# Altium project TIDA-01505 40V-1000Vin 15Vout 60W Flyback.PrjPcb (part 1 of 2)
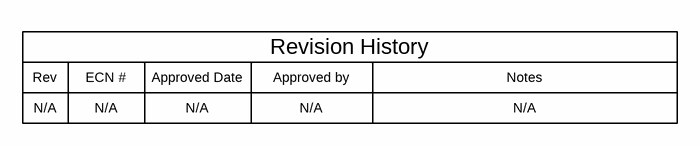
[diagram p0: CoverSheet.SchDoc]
CopyrightYear: 2017; PCB_Layout: X.Gong; PCB_Rev: E1; PRJ_Customer: Public Release; PRJ_Engineer: X.Gong; PRJ_Number: TIDA-01505; PRJ_Title: 40V-1000Vin 15Vout 60W Flyback; SCH_Rev: E1; TechSupport: http://www.ti.com/support; TID: TIDA-01505
4 sheets, 307 parts. Net scope: global (net labels, ports and power ports of the same name join across sheets).
Board file: TIDA-01505 PCB.PcbDoc
Sheets:
  CoverSheet.SchDoc
  Flyback_withOpto.SchDoc
  Flyback_PSR.SchDoc
  Hardware.SchDoc

## Sheet CoverSheet.SchDoc: Block Diagram
size A3; Date: Not shown in title block; ApprovedBy: Not shown in title block; CheckedBy: Not shown in title block; Author: Not shown in title block; CompanyName: Not shown in title block; DrawnBy: X.Gong; Engineer: Not shown in title block; Organization: Not shown in title block; Address1: Not shown in title block; Address2: Not shown in title block; Address3: Not shown in title block; Address4: Not shown in title block; DocumentNumber: 1; Revision: Use project parameter SCH_Rev; SheetNumber: 1; SheetTotal: 4; PageSetup: Record=PageOptions¦CenterHorizontal=True¦CenterVertical=True¦PrintScale=0.69¦XCorrection=1.00¦YCorrection=1.00¦PrintKind=0¦BorderSize=5000000¦LeftOffset=0¦BottomOffset=0¦Orientation=2¦PaperLength=1000¦PaperWidth=1000¦Scale=100¦PaperSource=15¦PrintQuality=600¦MediaType=1¦DitherType=10¦PaperKind=Letter¦PrintScaleMode=1

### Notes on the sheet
- Rev
- ECN #
- Approved Date
- Approved by
- Revision History
- Notes
- N/A

## Sheet Flyback_withOpto.SchDoc: Flyback_with_Optocoupler
size A3; Date: Not shown in title block; ApprovedBy: Not shown in title block; CheckedBy: Not shown in title block; Author: Not shown in title block; CompanyName: Not shown in title block; DrawnBy: X.Gong; Engineer: Not shown in title block; Organization: Not shown in title block; Address1: Not shown in title block; Address2: Not shown in title block; Address3: Not shown in title block; Address4: Not shown in title block; DocumentNumber: 1; Revision: Use project parameter SCH_Rev; SheetNumber: 3; SheetTotal: 4; PageSetup: Record=PageOptions¦CenterHorizontal=True¦CenterVertical=True¦PrintScale=0.69¦XCorrection=1.00¦YCorrection=1.00¦PrintKind=0¦BorderSize=5000000¦LeftOffset=0¦BottomOffset=0¦Orientation=2¦PaperLength=1000¦PaperWidth=1000¦Scale=100¦PaperSource=15¦PrintQuality=600¦MediaType=1¦DitherType=10¦PaperKind=Letter¦PrintScaleMode=1
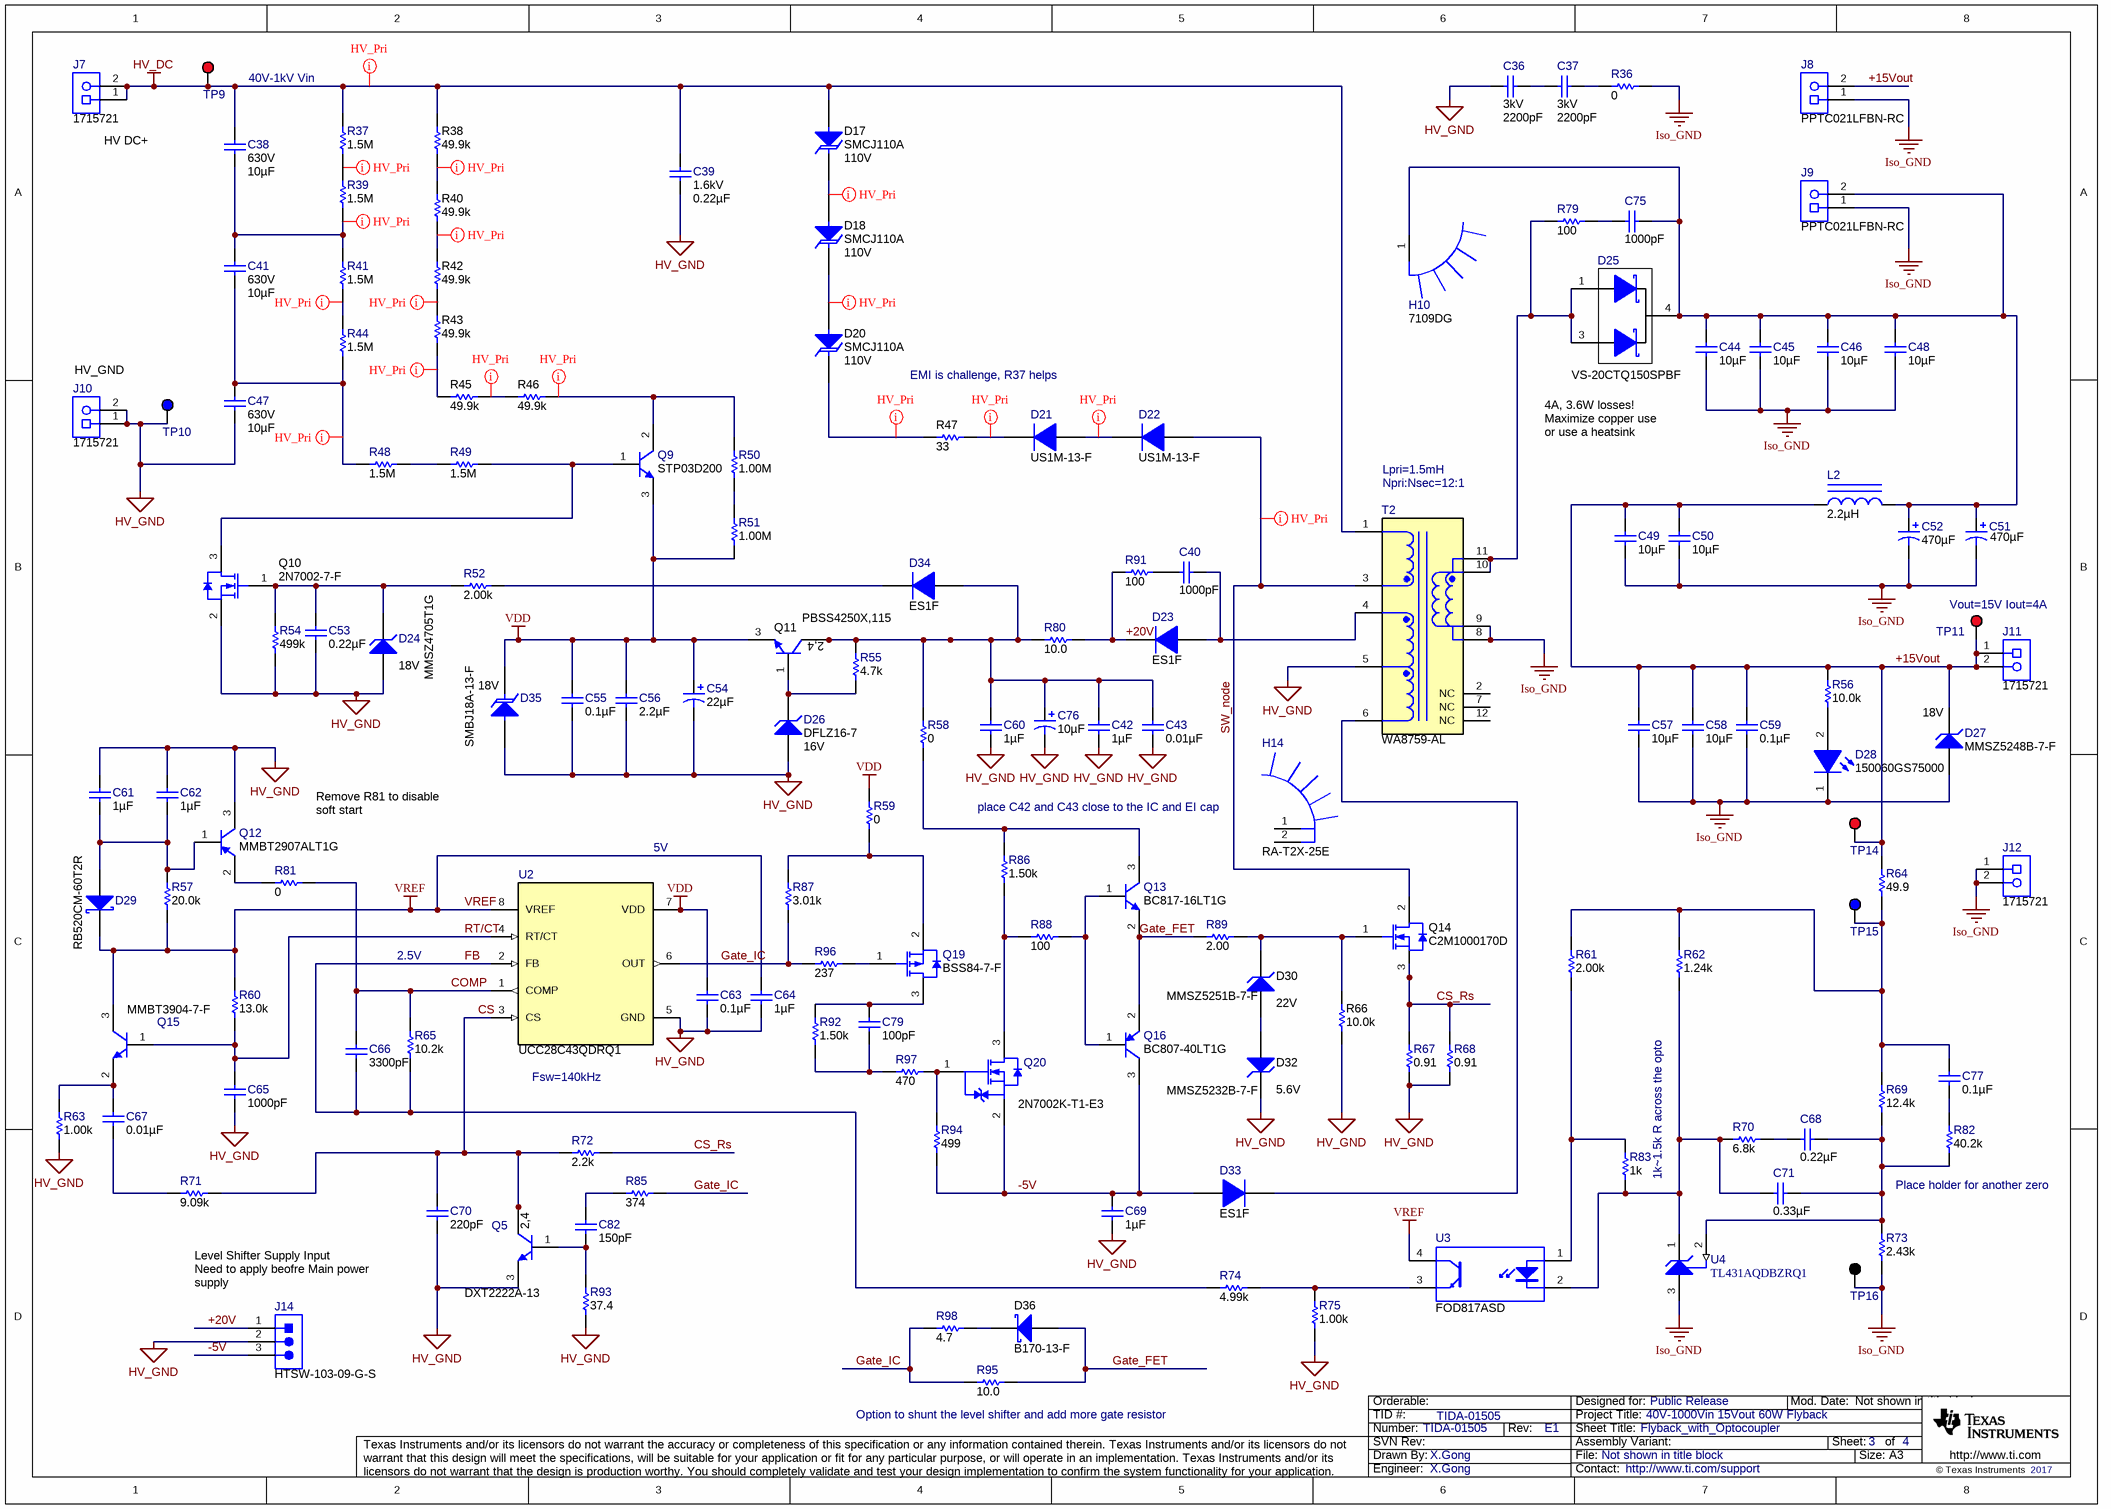
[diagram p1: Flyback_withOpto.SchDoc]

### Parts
C36  VDC_V: 3kV  ValueDisplayed: 2200pF  [CK45-RR_1650x600]  (hidden comment: CK45-R3FD222K-NRA)
C37  VDC_V: 3kV  ValueDisplayed: 2200pF  [CK45-RR_1650x600]  (hidden comment: CK45-R3FD222K-NRA)
C38  VDC_V: 630V  ValueDisplayed: 10µF  [B32776P_4200x1800x3250]  (hidden comment: B32776P6106K000)
C39  VDC_V: 1.6kV  ValueDisplayed: 0.22µF  [Kemet_3200x1800x3300]  (hidden comment: R76TR32204030J)
C40  ValueDisplayed: 1000pF  [1206]  (hidden comment: GRM31B5C2J102JW01L)
C41  VDC_V: 630V  ValueDisplayed: 10µF  [B32776P_4200x1800x3250]  (hidden comment: B32776P6106K000)
C42  ValueDisplayed: 1µF  [1206_180]  (hidden comment: GRM31CR72A105KA01L)
C43  ValueDisplayed: 0.01µF  [0805_HV]  (hidden comment: GRM21BR72A103KA01L)
C44  ValueDisplayed: 10µF  [0805_HV]  (hidden comment: GRM21BR6YA106KE43L)
C45  ValueDisplayed: 10µF  [0805_HV]  (hidden comment: GRM21BR6YA106KE43L)
C46  ValueDisplayed: 10µF  [0805_HV]  (hidden comment: GRM21BR6YA106KE43L)
C47  VDC_V: 630V  ValueDisplayed: 10µF  [B32776P_4200x1800x3250]  (hidden comment: B32776P6106K000)
C48  ValueDisplayed: 10µF  [0805_HV]  (hidden comment: GRM21BR6YA106KE43L)
C49  ValueDisplayed: 10µF  [0805_HV]  (hidden comment: GRM21BR6YA106KE43L)
C50  ValueDisplayed: 10µF  [0805_HV]  (hidden comment: GRM21BR6YA106KE43L)
C51  ValueDisplayed: 470µF  [Chemi-Con_1000x2000]  (hidden comment: EKZE350ELL471MJ20S)
C52  ValueDisplayed: 470µF  [Chemi-Con_1000x2000]  (hidden comment: EKZE350ELL471MJ20S)
C53  ValueDisplayed: 0.22µF  [0805_HV]  (hidden comment: GRM21BR71H224KA01L)
C54  ValueDisplayed: 22µF  [SM_RADIAL_D]  (hidden comment: EEE-FK1H220P)
C55  ValueDisplayed: 0.1µF  [0805_HV]  (hidden comment: C2012X7R1H104K085AA)
C56  ValueDisplayed: 2.2µF  [0805_HV]  (hidden comment: CGA4J3X7R1H225K125AB)
C57  ValueDisplayed: 10µF  [0805_HV]  (hidden comment: GRM21BR6YA106KE43L)
C58  ValueDisplayed: 10µF  [0805_HV]  (hidden comment: GRM21BR6YA106KE43L)
C59  ValueDisplayed: 0.1µF  [0805_HV]  (hidden comment: C2012X7R1H104K085AA)
C60  ValueDisplayed: 1µF  [1206_180]  (hidden comment: GRM31CR72A105KA01L)
C61  ValueDisplayed: 1µF  [0805_HV]  (hidden comment: GRM21BR71E105KA99L)
C62  ValueDisplayed: 1µF  [0805_HV]  (hidden comment: GRM21BR71E105KA99L)
C63  ValueDisplayed: 0.1µF  [0805_HV]  (hidden comment: C2012X7R1H104K085AA)
C64  ValueDisplayed: 1µF  [0603]  (hidden comment: GRM188R71E105KA12D)
C65  ValueDisplayed: 1000pF  [0805_HV]  (hidden comment: GCM2165C1H102JA16D)
C66  ValueDisplayed: 3300pF  [0805_HV]  (hidden comment: GRM2165C1H332JA01D)
C67  ValueDisplayed: 0.01µF  [0805_HV]  (hidden comment: GRM216R71H103KA01D)
C68  ValueDisplayed: 0.22µF  [0805_HV]  (hidden comment: GRM21BR71H224KA01L)
C69  ValueDisplayed: 1µF  [1206_180]  (hidden comment: GRM31CR72A105KA01L)
C70  ValueDisplayed: 220pF  [0805_HV]  (hidden comment: GRM2165C1H221JA01D)
C71  ValueDisplayed: 0.33µF  [0805_HV]  (hidden comment: GRM219R71H334KA88D)
C75  ValueDisplayed: 1000pF  [1206]  (hidden comment: GRM31B5C2J102JW01L)
C76  ValueDisplayed: 10µF  [SM_RADIAL_E]  (hidden comment: EEE-2AA100UP)
C77  ValueDisplayed: 0.1µF  [0805_HV]  (hidden comment: GCM21BR71H104KA37K)
C79  ValueDisplayed: 100pF  [0603]  (hidden comment: GRM1885C1H101JA01D)
C82  ValueDisplayed: 150pF  [0805_HV]  (hidden comment: GRM2165C1H151JA01D)
D17  SMCJ110A  value 110V  [SMC_265]
D18  SMCJ110A  value 110V  [SMC_265]
D20  SMCJ110A  value 110V  [SMC_265]
D21  US1M-13-F  [SMA]
D22  US1M-13-F  [SMA]
D23  ES1F  [SMA]
D24  MMSZ4705T1G  value 18V  [SOD-123]
D25  VS-20CTQ150SPBF  [DDPAK]
D26  DFLZ16-7  value 16V  [PowerDI123]
D27  MMSZ5248B-7-F  value 18V  [SOD-123]
D28  150060GS75000  [WL-SMCW_GREEN]
D29  RB520CM-60T2R  [SOD-923]
D30  MMSZ5251B-7-F  value 22V  [SOD-123]
D32  MMSZ5232B-7-F  value 5.6V  [SOD-123]
D33  ES1F  [SMA]
D34  ES1F  [SMA]
D35  SMBJ18A-13-F  value 18V  [SMB]
D36  B170-13-F  [SMA]
H10  7109DG  [Aavid_7109DG]
H14  RA-T2X-25E  [HSINK_RA-T2X-25E]
J7  1715721  [PhoenixContact_1715721]
J8  PPTC021LFBN-RC  [CONN_PPTC021LFBN-RC]
J9  PPTC021LFBN-RC  [CONN_PPTC021LFBN-RC]
J10  1715721  [PhoenixContact_1715721]
J11  1715721  [PhoenixContact_1715721]
J12  1715721  [PhoenixContact_1715721]
J14  HTSW-103-09-G-S  [Samtec_HTSW-103-09-x-S]
L2  ValueDisplayed: 2.2µH  [XAL6030]  (hidden comment: XAL6030-222MEB)
Q5  DXT2222A-13  [SOT-89-3]
Q9  STP03D200  [TO-220AB]
Q10  2N7002-7-F  [SOT-23]
Q11  PBSS4250X,115  [SOT-89-3]
Q12  MMBT2907ALT1G  [SOT-23]
Q13  BC817-16LT1G  [SOT-23]
Q14  C2M1000170D  [TO-247]
Q15  MMBT3904-7-F  [SOT-23]
Q16  BC807-40LT1G  [SOT-23]
Q19  BSS84-7-F  [SOT-23]
Q20  2N7002K-T1-E3  [SOT-23]
R36  ValueDisplayed: 0  [2010]  (hidden comment: CRCW20100000Z0EF)
R37  ValueDisplayed: 1.5M  [2010]  (hidden comment: ERJ12ZYJ155U)
R38  ValueDisplayed: 49.9k  [2010]  (hidden comment: CRCW201049K9FKEF)
R39  ValueDisplayed: 1.5M  [2010]  (hidden comment: ERJ12ZYJ155U)
R40  ValueDisplayed: 49.9k  [2010]  (hidden comment: CRCW201049K9FKEF)
R41  ValueDisplayed: 1.5M  [2010]  (hidden comment: ERJ12ZYJ155U)
R42  ValueDisplayed: 49.9k  [2010]  (hidden comment: CRCW201049K9FKEF)
R43  ValueDisplayed: 49.9k  [2010]  (hidden comment: CRCW201049K9FKEF)
R44  ValueDisplayed: 1.5M  [2010]  (hidden comment: ERJ12ZYJ155U)
R45  ValueDisplayed: 49.9k  [2010]  (hidden comment: CRCW201049K9FKEF)
R46  ValueDisplayed: 49.9k  [2010]  (hidden comment: CRCW201049K9FKEF)
R47  ValueDisplayed: 33  [2010]  (hidden comment: CRCW201033R0JNEF)
R48  ValueDisplayed: 1.5M  [2010]  (hidden comment: ERJ12ZYJ155U)
R49  ValueDisplayed: 1.5M  [2010]  (hidden comment: ERJ12ZYJ155U)
R50  ValueDisplayed: 1.00M  [2010]  (hidden comment: CRCW20101M00FKEF)
R51  ValueDisplayed: 1.00M  [2010]  (hidden comment: CRCW20101M00FKEF)
R52  ValueDisplayed: 2.00k  [0805_HV]  (hidden comment: CRCW08052K00FKEA)
R54  ValueDisplayed: 499k  [0603]  (hidden comment: CRCW0603499KFKEA)
R55  ValueDisplayed: 4.7k  [0603]  (hidden comment: CRCW06034K70JNEA)
R56  ValueDisplayed: 10.0k  [0603]  (hidden comment: CRCW060310K0FKEA)
R57  ValueDisplayed: 20.0k  [0805_HV]  (hidden comment: CRCW080520K0FKEA)
R58  ValueDisplayed: 0  [0805_HV]  (hidden comment: CRCW08050000Z0EA)
R59  ValueDisplayed: 0  [0805_HV]  (hidden comment: CRCW08050000Z0EA)
R60  ValueDisplayed: 13.0k  [0805_HV]  (hidden comment: CRCW080513K0FKEA)
R61  ValueDisplayed: 2.00k  [0805_HV]  (hidden comment: CRCW08052K00FKEA)
R62  ValueDisplayed: 1.24k  [0805_HV]  (hidden comment: CRCW08051K24FKEA)
R63  ValueDisplayed: 1.00k  [0805_HV]  (hidden comment: CRCW08051K00FKEA)
R64  ValueDisplayed: 49.9  [0805_HV]  (hidden comment: CRCW080549R9FKEA)
R65  ValueDisplayed: 10.2k  [0805_HV]  (hidden comment: CRCW080510K2FKEA)
R66  ValueDisplayed: 10.0k  [1206]  (hidden comment: CRCW120610K0FKEA)
R67  ValueDisplayed: 0.91  [2010]  (hidden comment: CRM2010-FX-R910ELF)
R68  ValueDisplayed: 0.91  [2010]  (hidden comment: CRM2010-FX-R910ELF)
R69  ValueDisplayed: 12.4k  [0805_HV]  (hidden comment: CRCW080512K4FKEA)
R70  ValueDisplayed: 6.8k  [0805_HV]  (hidden comment: CRCW08056K80JNEA)
R71  ValueDisplayed: 9.09k  [0805_HV]  (hidden comment: CRCW08059K09FKEA)
R72  ValueDisplayed: 2.2k  [0805_HV]  (hidden comment: CRCW08052K20JNEA)
R73  ValueDisplayed: 2.43k  [0805_HV]  (hidden comment: CRCW08052K43FKEA)
R74  ValueDisplayed: 4.99k  [0805_HV]  (hidden comment: CRCW08054K99FKEA)
R75  ValueDisplayed: 1.00k  [0805_HV]  (hidden comment: CRCW08051K00FKEA)
R79  ValueDisplayed: 100  [1206]  (hidden comment: CRCW1206100RFKEA)
R80  ValueDisplayed: 10.0  [1206]  (hidden comment: CRCW120610R0FKEA)
R81  ValueDisplayed: 0  [0805_HV]  (hidden comment: CRCW08050000Z0EA)
R82  ValueDisplayed: 40.2k  [0805_HV]  (hidden comment: CRCW080540K2FKEA)
R83  ValueDisplayed: 1k  [0805_HV]  (hidden comment: CRCW08052K05FKEA)
R85  ValueDisplayed: 374  [0805_HV]  (hidden comment: CRCW0805374RFKEA)
R86  ValueDisplayed: 1.50k  [2010]  (hidden comment: CRCW20101K50FKEF)
R87  ValueDisplayed: 3.01k  [0805_HV]  (hidden comment: CRCW08053K01FKEA)
R88  ValueDisplayed: 100  [0805_HV]  (hidden comment: CRCW0805100RFKEA)
R89  ValueDisplayed: 2.00  [2010]  (hidden comment: CRCW20102R00FKEF)
R91  ValueDisplayed: 100  [1206]  (hidden comment: CRCW1206100RFKEA)
R92  ValueDisplayed: 1.50k  [2010]  (hidden comment: CRCW20101K50FKEF)
R93  ValueDisplayed: 37.4  [0805_HV]  (hidden comment: CRCW080537R4FKEA)
R94  ValueDisplayed: 499  [0805_HV]  (hidden comment: CRCW0805499RFKEA)
R95  ValueDisplayed: 10.0  [1206]  (hidden comment: CRCW120610R0FKEA)
R96  ValueDisplayed: 237  [0805_HV]  (hidden comment: CRCW0805237RFKEA)
R97  ValueDisplayed: 470  [0805_HV]  (hidden comment: CRCW0805470RFKEA)
R98  ValueDisplayed: 4.7  [1206]  (hidden comment: CRCW12064R70JNEA)
T2  WA8759-AL  [Coilcraft_WA8537-BL]
TP9  5005  [Keystone5005]  (value not drawn)
TP10  5122  [Keystone5122]  (value not drawn)
TP11  5005  [Keystone5005]  (value not drawn)
TP14  5005  [Keystone5005]  (value not drawn)
TP15  5122  [Keystone5122]  (value not drawn)
TP16  5006  [Keystone5006]  (value not drawn)
U2  UCC28C43QDRQ1  [D0008A_N]
U3  FOD817ASD  [N04C]
U4  TL431AQDBZRQ1  [DBZ0003A_N]

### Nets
HV_DC: C38.1 C39.1 D17.2(A) J7.1 J7.2 R37.2 R38.2 T2.1 TP9.1
HV_GND: C36.2 C39.2 C42.2 C43.2 C47.2 C53.2 C54.2(-) C55.2 C56.2 C60.2 C61.1 C62.1 C63.2 C64.2 C65.2 C69.2 C70.2 C76.2(-) D24.2(A) D26.2(A) D32.1(K) D35.2(A) J10.1 J10.2 J14.2 Q5.3(E) Q10.2(S) Q12.3(C) R54.1 R63.1 R66.1 R67.1 R68.1 R75.1 R93.1 T2.5 TP10.1 U2.5(GND)
Iso_GND: C44.2 C45.2 C46.2 C48.2 C49.2 C50.2 C51.2(-) C52.2(-) C57.2 C58.2 C59.2 D27.2(A) D28.1(K) J8.1 J9.1 J12.1 J12.2 R36.2 R73.1 T2.8 T2.9 TP16.1 U4.3(ANODE)
VDD: C54.1(+) C55.1 C56.1 C63.1 D35.1(K) Q9.3(E) Q11.3(E) R51.1 R59.2 U2.7(VDD)
VREF: C64.1 D29.1(K) Q15.3(C) R57.1 R60.2 U2.8(VREF) U3.4(C)
+15Vout: C49.1 C50.1 C57.1 C58.1 C59.1 D27.1(K) J8.2 J11.1 J11.2 L2.1 R56.2 R64.2 TP11.1 TP14.1
+20V: D23.1(K) J14.1 R80.2 R91.1
-5V: C69.1 D33.2(A) J14.3 Q16.3(C) Q20.2(S) R94.1
COMP: C66.1 R65.2 R81.2 U2.1(COMP)
CS: C70.1 Q5.2(C) Q5.4(C) R71.2 R72.1 U2.3(CS)
CS_Rs: Q14.3(S) R67.2 R68.2 R72.2
FB: C66.2 R65.1 R74.1 U2.2(FB)
Gate_FET: D36.2(A) Q13.2(E) Q16.2(E) R89.1 R95.2
Gate_IC: R85.1 R87.1 R95.1 R96.1 R98.1 U2.6(OUT)
RT/CT: C65.1 Q15.1(B) R60.1 U2.4(RT/CT)
SW_node: D22.2(A) Q14.2(D) T2.3
NetC36_1: C36.1 C37.2
NetC37_1: C37.1 R36.1
NetC38_2: C38.2 C41.1 R39.1 R41.2
NetC40_1: C40.1 D23.2(A) T2.4
NetC40_2: C40.2 R91.2
NetC41_2: C41.2 C47.1 R44.1 R48.2
NetC42_1: C42.1 C43.1 C60.1 C76.1(+) D34.2(A) Q11.2(C) Q11.4(C) R55.2 R58.2 R80.1
NetC44_1: C44.1 C45.1 C46.1 C48.1 C51.1(+) C52.1(+) C75.1 D25.4(K) H10.1 J9.2 L2.2
NetC53_1: C53.1 D24.1(K) Q10.1(G) R52.1 R54.2
NetC61_2: C61.2 C62.2 D29.2(A) Q12.1(B) R57.2
NetC67_1: C67.1 Q15.2(E) R63.2
NetC67_2: C67.2 R71.1
NetC68_1: C68.1 C71.1 R69.1 R73.2 R82.1 U4.2(REF)
NetC68_2: C68.2 R70.2
NetC71_2: C71.2 R62.1 R70.1 R83.1 U3.2(K) U4.1(CATHODE)
NetC75_2: C75.2 R79.2
NetC77_1: C77.1 R61.2 R62.2 R64.1 R69.2 TP15.1
NetC77_2: C77.2 R82.2
NetC79_1: C79.1 Q19.3(D) R92.2
NetC79_2: C79.2 R92.1 R97.1
NetC82_1: C82.1 R85.2
NetC82_2: C82.2 Q5.1(B) R93.2
NetD17_1: D17.1(K) D18.2(A)
NetD18_1: D18.1(K) D20.2(A)
NetD20_1: D20.1(K) R47.1
NetD21_1: D21.1(K) R47.2
NetD21_2: D21.2(A) D22.1(K)
NetD25_1: D25.1(A) D25.3(A) R79.1 T2.10 T2.11
NetD26_1: D26.1(K) Q11.1(B) R55.1
NetD28_2: D28.2(A) R56.1
NetD30_1: D30.1(K) Q14.1(G) R66.2 R89.2
NetD30_2: D30.2(A) D32.2(A)
NetD33_1: D33.1(K) T2.6
NetD34_1: D34.1(K) R52.2
NetD36_1: D36.1(K) R98.2
NetQ9_1: Q9.1(B) Q10.3(D) R49.1
NetQ9_2: Q9.2(C) R46.1 R50.2
NetQ12_2: Q12.2(E) R81.1
NetQ13_1: Q13.1(B) Q16.1(B) R88.2
NetQ13_3: Q13.3(C) R58.1 R86.2
NetQ19_1: Q19.1(G) R96.2
NetQ19_2: Q19.2(S) R59.1 R87.2
NetQ20_1: Q20.1(G) R94.2 R97.2
NetQ20_3: Q20.3(D) R86.1 R88.1
NetR37_1: R37.1 R39.2
NetR38_1: R38.1 R40.2
NetR40_1: R40.1 R42.2
NetR41_1: R41.1 R44.2
NetR42_1: R42.1 R43.2
NetR43_1: R43.1 R45.2
NetR45_1: R45.1 R46.2
NetR48_1: R48.1 R49.2
NetR50_1: R50.1 R51.2
NetR61_1: R61.1 R83.2 U3.1(A)
NetR74_2: R74.2 R75.2 U3.3(E)

Not connected (* = marked no-connect by the designer): H14 1 2; T2 2(NC) 7(NC) 12(NC)

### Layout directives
net class 1500V: HV_DC, NetC38_2, NetC41_2, NetD17_1, NetD18_1, NetD20_1, NetD21_1, NetD21_2, NetQ9_2, NetR37_1, NetR38_1, NetR40_1, NetR41_1, NetR42_1, NetR43_1, NetR45_1, SW_node

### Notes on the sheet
- 40V-1kV Vin
- (near J7) HV DC+
- (near J10) HV_GND
- EMI is challenge, R37 helps
- 4A, 3.6W losses! Maximize copper use
  or use a heatsink
- (near T2) Npri:Nsec=12:1
- Lpri=1.5mH
- (near TP11) Vout=15V Iout=4A
- Remove R81 to disable soft start
- 5V
- place C42 and C43 close to the IC and EI cap
- 2.5V
- Fsw=140kHz
- (near R83) 1k
  .5k R across the opto
- Place holder for another zero
- Level Shifter Supply Input
  Need to apply beofre Main power supply
- (near R95) Option to shunt the level shifter and add more gate resistor

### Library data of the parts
C36 C37 = CMP-0074791-1: CAP, CERM, 2200 pF, 3000 V,+/- 10%, ?, 16.5x6mm; Manufacturer: TDK; TaMin_C: -25°C; Polarized: N; TempCo: R; SizeAreaWB_mm2: 148.0; U/M: EA; Value: 2200pF; TaMax_C: 125°C; SizeZ_mm: 20.5; SizeX_mm: 16.5; SizeY_mm: 6.0; Value2: 3000V; SizeArea_mm2: 99.0; Cap_F: 2.2nF; AEC Category: Q200
C38 C41 C47 = CMP-0074803-1: CAP, Film, 10 µF, 630 V,+/- 10%, 0.007 ohm, AEC-Q200 Grade 1, TH; Manufacturer: TDK; TaMin_C: -40°C; ESR_ohm: 7m; Polarized: N; SizeAreaWB_mm2: 880.0; U/M: EA; Value: 10uF; TaMax_C: 125°C; SizeZ_mm: 32.5; SizeX_mm: 42.0; SizeY_mm: 18.0; Cap_Case: 42x18x32.5mm; SizeArea_mm2: 756.0; AEC Qualified: Y; IRMS_A: 9.6A; AEC Grade: 1; AEC Category: Q200
C39 = CMP-0077096-1: CAP, Film, 0.22 µF, 1600 V,+/- 5%, AEC-Q200 Grade 2, TH; Manufacturer: Kemet; Cap_F: 220nF; SizeAreaWB_mm2: 680.0; SizeArea_mm2: 576.0; AEC Qualified: Y; AEC Category: Q200; Value: 0.22uF; TaMax_C: 105°C; SizeZ_mm: 33.1; AEC Grade: 2; Polarized: N; TaMin_C: -55°C; SizeY_mm: 18.0; Value2: 1600V; U/M: EA; SizeX_mm: 32.0; Cap_Case: 32x18x33mm
C40 C75 = GRM31B5C2J102JW01L: CAP, CERM, 1000 pF, 630 V,+/- 5%, C0G/NP0, 1206; Manufacturer: MuRata; Polarized: N; CompType: Capacitor; Value: 1000pF; U/M: EA; Cap_F: 0.000000001; Tolerance_%: 5; VDC_V: 630; Value2: 630V; TaMin_C: -55; TaMax_C: 125; SizeArea_mm2: 5.12; SizeAreaWB_mm2: 10.92; SizeX_mm: 3.2; SizeY_mm: 1.6; SizeZ_mm: 1.35; AEC Category: Q200; Green_Lifecycle: Not Set; Green_REACh: Incomplete
C42 C60 C69 = GRM31CR72A105KA01L: CAP, CERM, 1 µF, 100 V,+/- 10%, X7R, 1206; Manufacturer: MuRata; Polarized: N; CompType: Capacitor; Value: 1uF; U/M: EA; Cap_F: 0.000001; Tolerance_%: 10; VDC_V: 100; Value2: 100V; TaMin_C: -55; TaMax_C: 125; Cap_Case: 1206; SizeArea_mm2: 5.12; SizeAreaWB_mm2: 10.92; SizeX_mm: 3.2; SizeY_mm: 1.6; SizeZ_mm: 1.8; AEC Category: Q200; Green_Lifecycle: Active; Green_REACh: Passed
C43 = GRM21BR72A103KA01L: CAP, CERM, 0.01 µF, 100 V,+/- 10%, X7R, 0805; Manufacturer: MuRata; Polarized: N; CompType: Capacitor; Value: 0.01uF; U/M: EA; Cap_F: 0.00000001; Tolerance_%: 10; VDC_V: 100; Value2: 100V; TaMin_C: -55; TaMax_C: 125; Cap_Case: 0805; SizeArea_mm2: 2.5; SizeAreaWB_mm2: 6.75; SizeX_mm: 2; SizeY_mm: 1.25; SizeZ_mm: 1.45; AEC Category: Q200; Green_Lifecycle: Active; Green_REACh: Passed
C44-C46 C48-C50 C57 C58 = GRM21BR6YA106KE43L: CAP, CERM, 10 µF, 35 V,+/- 10%, X5R, 0805; Manufacturer: MuRata; Polarized: N; CompType: Capacitor; Value: 10uF; U/M: EA; Cap_F: 0.00001; Tolerance_%: 10; VDC_V: 35; Value2: 35V; TaMin_C: -55; TaMax_C: 85; Cap_Case: 0805; SizeArea_mm2: 2.5; SizeAreaWB_mm2: 6.75; SizeX_mm: 2; SizeY_mm: 1.25; SizeZ_mm: 1.45; AEC Category: Q200; Green_Lifecycle: Active; Green_REACh: Passed
C51 C52 = EKZE350ELL471MJ20S: CAP, AL, 470 µF, 35 V, +/- 20%, TH; Manufacturer: Chemi-Con; Polarized: Y; CompType: Capacitor; Value: 470uF; U/M: EA; Cap_F: 0.00047; Tolerance_%: 20; VDC_V: 35; Value2: 35V; IRMS_A: 1.82; TaMin_C: -40; TaMax_C: 105; Cap_Case: 10x20; SizeAreaWB_mm2: 144; SizeArea_mm2: 100; SizeX_mm: 10; SizeZ_mm: 21.5; AEC Category: Q200; AEC Qualified: N
C53 C68 = GRM21BR71H224KA01L: CAP, CERM, 0.22 µF, 50 V,+/- 10%, X7R, 0805; Manufacturer: MuRata; Polarized: N; CompType: Capacitor; Value: 0.22uF; U/M: EA; Cap_F: 0.00000022; Tolerance_%: 10; VDC_V: 50; Value2: 50V; TaMin_C: -55; TaMax_C: 125; Cap_Case: 0805; SizeArea_mm2: 2.5; SizeAreaWB_mm2: 6.75; SizeX_mm: 2; SizeY_mm: 1.25; SizeZ_mm: 1.45; AEC Category: Q200; Green_Lifecycle: Active; Green_REACh: Passed
C54 = EEE-FK1H220P: CAP, AL, 22 µF, 50 V, +/- 20%, 0.88 ohm, AEC-Q200 Grade 2, SMD; Manufacturer: Panasonic; Polarized: Y; CompType: Capacitor; Value: 22uF; U/M: EA; Cap_F: 0.000022; Tolerance_%: 20; VDC_V: 50; Value2: 50V; ESR_ohm: 0.88; IRMS_A: 0.165; TaMin_C: -55; TaMax_C: 105; Cap_Case: D; SizeAreaWB_mm2: 84.28; SizeArea_mm2: 51.48; SizeX_mm: 7.8; SizeY_mm: 6.6; SizeZ_mm: 5.4; AEC Category: Q200; AEC Grade: 2; Green_Lifecycle: Active; Green_REACh: Passed
C55 C59 C63 = C2012X7R1H104K085AA: CAP, CERM, 0.1 µF, 50 V,+/- 10%, X7R, 0805; Manufacturer: TDK; Polarized: N; CompType: Capacitor; Value: 0.1uF; U/M: EA; Cap_F: 0.0000001; Tolerance_%: 10; ESR_ohm: 0.02619; Value1: 0.02619 ohm; VDC_V: 50; Value2: 50V; IRMS_A: 1.29514; TaMin_C: -55; TaMax_C: 125; Cap_Case: 0805; SizeArea_mm2: 2.5; SizeAreaWB_mm2: 6.75; SizeX_mm: 2; SizeY_mm: 1.25; SizeZ_mm: 1.45; AEC Category: Q200; Green_Lifecycle: NRND; Green_REACh: Passed
C56 = CGA4J3X7R1H225K125AB: CAP, CERM, 2.2 µF, 50 V,+/- 10%, X7R, AEC-Q200 Grade 1, 0805; Manufacturer: TDK; Polarized: N; CompType: Capacitor; Value: 2.2uF; U/M: EA; Cap_F: 0.0000022; Tolerance_%: 10; ESR_ohm: 0.003288; Value1: 0.003288 ohm; VDC_V: 50; Value2: 50V; IRMS_A: 3.60029; TaMin_C: -55; TaMax_C: 125; Cap_Case: 0805; SizeArea_mm2: 2.5; SizeAreaWB_mm2: 6.75; SizeX_mm: 2; SizeY_mm: 1.25; SizeZ_mm: 1.45; AEC Category: Q200; AEC Qualified: Y; AEC Grade: 1
C61 C62 = GRM21BR71E105KA99L: CAP, CERM, 1 µF, 25 V,+/- 10%, X7R, 0805; Manufacturer: MuRata; Polarized: N; CompType: Capacitor; Value: 1uF; U/M: EA; Cap_F: 0.000001; Tolerance_%: 10; VDC_V: 25; Value2: 25V; TaMin_C: -55; TaMax_C: 125; Cap_Case: 0805; SizeArea_mm2: 2.5; SizeAreaWB_mm2: 6.75; SizeX_mm: 2; SizeY_mm: 1.25; SizeZ_mm: 1.45; AEC Category: Q200; Green_Lifecycle: Active; Green_REACh: Passed
C64 = GRM188R71E105KA12D: CAP, CERM, 1 µF, 25 V,+/- 10%, X7R, 0603; Manufacturer: MuRata; Polarized: N; CompType: Capacitor; Value: 1uF; U/M: EA; Cap_F: 0.000001; Tolerance_%: 10; VDC_V: 25; Value2: 25V; TaMin_C: -55; TaMax_C: 125; SizeArea_mm2: 1.28; SizeAreaWB_mm2: 4.68; SizeX_mm: 1.6; SizeY_mm: 0.8; SizeZ_mm: 1; AEC Category: Q200; Green_Lifecycle: Active; Green_REACh: Passed
C65 = GCM2165C1H102JA16D: CAP, CERM, 1000 pF, 50 V,+/- 5%, C0G/NP0, AEC-Q200 Grade 1, 0805; Manufacturer: MuRata; Polarized: N; CompType: Capacitor; Value: 1000pF; U/M: EA; Cap_F: 0.000000001; Tolerance_%: 5; VDC_V: 50; Value2: 50V; TaMin_C: -55; TaMax_C: 125; Cap_Case: 0805; SizeArea_mm2: 2.5; SizeAreaWB_mm2: 6.75; SizeX_mm: 2; SizeY_mm: 1.25; SizeZ_mm: 1.45; AEC Category: Q200; AEC Qualified: Y; AEC Grade: 1
C66 = GRM2165C1H332JA01D: CAP, CERM, 3300 pF, 50 V,+/- 5%, C0G/NP0, 0805; Manufacturer: MuRata; Polarized: N; CompType: Capacitor; Value: 3300pF; U/M: EA; Cap_F: 0.0000000033; Tolerance_%: 5; VDC_V: 50; Value2: 50V; TaMin_C: -55; TaMax_C: 125; Cap_Case: 0805; SizeArea_mm2: 2.5; SizeAreaWB_mm2: 6.75; SizeX_mm: 2; SizeY_mm: 1.25; SizeZ_mm: 1.45; AEC Category: Q200
C67 = GRM216R71H103KA01D: CAP, CERM, 0.01 µF, 50 V,+/- 10%, X7R, 0805; Manufacturer: MuRata; Polarized: N; CompType: Capacitor; Value: 0.01uF; U/M: EA; Cap_F: 0.00000001; Tolerance_%: 10; VDC_V: 50; Value2: 50V; TaMin_C: -55; TaMax_C: 125; Cap_Case: 0805; SizeArea_mm2: 2.5; SizeAreaWB_mm2: 6.75; SizeX_mm: 2; SizeY_mm: 1.25; SizeZ_mm: 1.45; AEC Category: Q200; Green_Lifecycle: Active; Green_REACh: Passed
C70 = GRM2165C1H221JA01D: CAP, CERM, 220 pF, 50 V,+/- 5%, C0G/NP0, 0805; Manufacturer: MuRata; Polarized: N; CompType: Capacitor; Value: 220pF; U/M: EA; Cap_F: 0.00000000022; Tolerance_%: 5; VDC_V: 50; Value2: 50V; TaMin_C: -55; TaMax_C: 125; Cap_Case: 0805; SizeArea_mm2: 2.5; SizeAreaWB_mm2: 6.75; SizeX_mm: 2; SizeY_mm: 1.25; SizeZ_mm: 1.45; AEC Category: Q200
C71 = GRM219R71H334KA88D: CAP, CERM, 0.33 µF, 50 V,+/- 10%, X7R, 0805; Manufacturer: MuRata; Polarized: N; CompType: Capacitor; Value: 0.33uF; U/M: EA; Cap_F: 0.00000033; Tolerance_%: 10; VDC_V: 50; Value2: 50V; TaMin_C: -55; TaMax_C: 125; Cap_Case: 0805; SizeArea_mm2: 2.5; SizeAreaWB_mm2: 6.75; SizeX_mm: 2; SizeY_mm: 1.25; SizeZ_mm: 1.45; AEC Category: Q200; Green_Lifecycle: Active; Green_REACh: Passed
C76 = EEE-2AA100UP: CAP, AL, 10 µF, 100 V, +/- 20%, AEC-Q200 Grade 3, SMD; Manufacturer: Panasonic; Polarized: Y; CompType: Capacitor; Value: 10uF; U/M: EA; Cap_F: 0.00001; Tolerance_%: 20; VDC_V: 100; Value2: 100V; IRMS_A: 0.05; TaMin_C: -40; TaMax_C: 85; Cap_Case: 8.0x6.0mm; SizeAreaWB_mm2: 118.45; SizeArea_mm2: 78.85; SizeX_mm: 9.5; SizeY_mm: 8.3; SizeZ_mm: 6.2; AEC Category: Q200; AEC Grade: 3
C77 = GCM21BR71H104KA37K: CAP, CERM, 0.1 µF, 50 V,+/- 10%, X7R, AEC-Q200 Grade 1, 0805; Manufacturer: MuRata; Polarized: N; CompType: Capacitor; Value: 0.1uF; U/M: EA; Cap_F: 0.0000001; Tolerance_%: 10; VDC_V: 50; Value2: 50V; TaMin_C: -55; TaMax_C: 125; Cap_Case: 0805; SizeArea_mm2: 2.5; SizeAreaWB_mm2: 6.75; SizeX_mm: 2; SizeY_mm: 1.25; SizeZ_mm: 1.45; AEC Category: Q200; AEC Qualified: Y; AEC Grade: 1
C79 = GRM1885C1H101JA01D: CAP, CERM, 100 pF, 50 V,+/- 5%, C0G/NP0, 0603; Manufacturer: MuRata; Polarized: N; CompType: Capacitor; Value: 100pF; U/M: EA; Cap_F: 0.0000000001; Tolerance_%: 5; VDC_V: 50; Value2: 50V; TaMin_C: -55; TaMax_C: 125; SizeArea_mm2: 1.28; SizeAreaWB_mm2: 4.68; SizeX_mm: 1.6; SizeY_mm: 0.8; SizeZ_mm: 1; AEC Category: Q200; Green_Lifecycle: Active; Green_REACh: Passed
C82 = GRM2165C1H151JA01D: CAP, CERM, 150 pF, 50 V,+/- 5%, C0G/NP0, 0805; Manufacturer: MuRata; Polarized: N; CompType: Capacitor; Value: 150pF; U/M: EA; Cap_F: 0.00000000015; Tolerance_%: 5; VDC_V: 50; Value2: 50V; TaMin_C: -55; TaMax_C: 125; Cap_Case: 0805; SizeArea_mm2: 2.5; SizeAreaWB_mm2: 6.75; SizeX_mm: 2; SizeY_mm: 1.25; SizeZ_mm: 1.45; AEC Category: Q200
D17 D18 D20 = SMCJ110A: Diode, TVS, Uni, 110 V, SMC; Manufacturer: Littelfuse; U/M: EA; Power_W: 6.5; Vr_V: 110; Value1: 6.5W; RJA_CperW: 75; SizeAreaWB_mm2: 78.5757; SizeArea_mm2: 46.8857; SizeX_mm: 7.94; SizeY_mm: 5.905; SizeZ_mm: 2.62; AEC Category: Q101
D21 D22 = US1M-13-F: Diode, Ultrafast, 1000 V, 1 A, SMA; Manufacturer: Diodes Inc.; U/M: EA; Vf_V: 1.7; Value: 1000V; Value1: 1A; Value2: 1.7V; Io_A: 1; Vr_V: 1000; TJmax_C: 150; RJC_CperW: 30; SizeAreaWB_mm2: 37.3428; SizeArea_mm2: 16.3228; SizeX_mm: 5.59; SizeY_mm: 2.92; SizeZ_mm: 2.87; AEC Category: Q101; Green_Lifecycle: Not Set; Green_REACh: Incomplete
D23 D33 D34 = CMP-0074851-1: Diode, Fast Rectifier, 300 V, 1 A, SMA; Manufacturer: Fairchild Semiconductor; Io_A: 1A; Green_Lifecycle: Active; SizeAreaWB_mm2: 37.3428; Vr_V: 300V; Green_REACh: Passed; TJmax_C: 150°C; U/M: EA; Value: 300V; SizeZ_mm: 2.87; SizeX_mm: 5.59; SizeY_mm: 2.92; Vf_V: 1.3V; SizeArea_mm2: 16.3228; AEC Qualified: N; AEC Category: Q101; RJC_CperW: 35.0
D24 = MMSZ4705T1G: Diode, Zener, 18 V, 500 mW, SOD-123; Manufacturer: ON Semiconductor; SymbolCreator: a0412235; U/M: EA; Power_W: 0.5; Vz_V: 18; Value1: 0.5W; RJA_CperW: 340; SizeAreaWB_mm2: 13.095; SizeArea_mm2: 6.545; SizeX_mm: 3.85; SizeY_mm: 1.7; SizeZ_mm: 1.35; AEC Category: Q101
D25 = VS-20CTQ150SPBF: Diode, Schottky, 150 V, 10 A, DDPAK; Manufacturer: Vishay-Semiconductor; U/M: EA; Vf_V: 0.66; Value: 150V; Value1: 10A; Value2: 0.66V; Io_A: 10; Vr_V: 150; TJmax_C: 175; SizeAreaWB_mm2: 209.6992; SizeArea_mm2: 154.8892; SizeX_mm: 15.245; SizeY_mm: 10.16; SizeZ_mm: 4.445; AEC Category: Q101; Green_Lifecycle: Not Set; Green_REACh: Incomplete
D26 = DFLZ16-7: Diode, Zener, 16 V, 1 W, PowerDI123; Manufacturer: Diodes Inc.; SymbolCreator: a0412235; U/M: EA; Power_W: 1; Vz_V: 16; Value1: 1W; RJA_CperW: 110; SizeAreaWB_mm2: 13.066; SizeArea_mm2: 6.586; SizeX_mm: 3.7; SizeY_mm: 1.78; SizeZ_mm: 0.98; AEC Category: Q101
D27 = CMP-0005755-2: Diode, Zener, 18 V, 500 mW, SOD-123; Manufacturer: Diodes Inc.; Power_W: 500mW; SizeAreaWB_mm2: 13.095; Value1: 0.5W; RJA_CperW: 350; U/M: EA; SizeZ_mm: 1.35; SizeX_mm: 3.85; SizeY_mm: 1.7; SizeArea_mm2: 6.545; AEC Category: Q101
D28 = CMP-0002905-1: LED, Green, SMD; Manufacturer: Wurth Elektronik; Io_A: 20mA; Tjmax_C: 85°C; Value1: W; U/M: EA; Angle: 140; Vf_V: 3.2V; Type: InGaN
D29 = RB520CM-60T2R: Diode, Schottky, 60 V, 0.1 A, SOD-923; Manufacturer: Rohm; U/M: EA; Value: 60V; Value1: 0.1A; Io_A: 0.1; Vr_V: 60; TJmax_C: 150; SizeAreaWB_mm2: 3.2; SizeArea_mm2: 0.6; SizeX_mm: 1; SizeZ_mm: 0.4; AEC Category: Q101; AEC Qualified: N
D30 = MMSZ5251B-7-F: Diode, Zener, 22 V, 500 mW, SOD-123; Manufacturer: Diodes Inc.; SymbolCreator: a0412235; U/M: EA; Power_W: 0.5; Vz_V: 22; Value1: 0.5W; RJA_CperW: 350; SizeAreaWB_mm2: 13.095; SizeArea_mm2: 6.545; SizeX_mm: 3.85; SizeY_mm: 1.7; SizeZ_mm: 1.35; AEC Category: Q101
D32 = MMSZ5232B-7-F: Diode, Zener, 5.6 V, 500 mW, SOD-123; Manufacturer: Diodes Inc.; SymbolCreator: a0412235; U/M: EA; Power_W: 0.5; Vz_V: 5.6; Value1: 0.5W; RJA_CperW: 350; SizeAreaWB_mm2: 13.095; SizeArea_mm2: 6.545; SizeX_mm: 3.85; SizeY_mm: 1.7; SizeZ_mm: 1.35; AEC Category: Q101; Green_Lifecycle: Active; Green_REACh: Passed
D35 = CMP-0005551-2: Diode, TVS, Uni, 18 V, 29.2 Vc, SMB; Manufacturer: Diodes Inc.; Power_W: 5W; SizeAreaWB_mm2: 44.156; U/M: EA; SizeZ_mm: 2.6; SizeX_mm: 5.6; SizeY_mm: 3.81; SizeArea_mm2: 21.336; AEC Category: Q101
D36 = B170-13-F: Diode, Schottky, 70 V, 1 A, SMA; Manufacturer: Diodes Inc.; U/M: EA; Vf_V: 0.79; Value: 70V; Value1: 1A; Value2: 0.79V; Io_A: 1; Vr_V: 70; TJmax_C: 150; RJC_CperW: 25; SizeAreaWB_mm2: 37.3428; SizeArea_mm2: 16.3228; SizeX_mm: 5.59; SizeY_mm: 2.92; SizeZ_mm: 2.87; AEC Category: Q101; Green_Lifecycle: Active; Green_REACh: Passed
H10 = CMP-0004038-1: Surface mount heat sink for D2PAK; Manufacturer: Aavid
H14 = CMP-0076741-1: Heatsink, TO-220, TO-218, TO-247; Manufacturer: Ohmite
J7 J10-J12 = CMP-0055471-1: Terminal Block, 5.08 mm, 2x1, TH; Manufacturer: Phoenix Contact; Cert_VDE: Y; CNHeader: FALSE; Current_A: 17.5A; Green_Lifecycle: Not Set; Gender: Female; Cert_CULUS: N; Green_REACh: Incomplete; Voltage_V: 400V; Row_Count: 1; Pitch_mm: 5.08; ContactFinish: Tin; CT: TRUE
J8 J9 = CMP-0054631-1: Receptacle, 100mil, 2x1, Tin, TH; Manufacturer: Sullins Connector Solutions; CNHeader: FALSE; Current_A: 3A; Gender: Female; Voltage_V: 250V; CompType: Socket Strip; Pitch_mm: 2.54; CT: TRUE; Cert_UL: Y
J14 = HTSW-103-09-G-S: Header, 100mil, 3x1, Gold, TH; Manufacturer: Samtec; SymbolCreator: a0799628; Pitch_mm: 2.54; Gender: Male; Row_Count: 1; Cert_CSA: Y
L2 = XAL6030-222MEB: Inductor, Shielded, Composite, 2.2 µH, 12.7 A, 0.012 ohm, SMD; Manufacturer: Coilcraft; Value: 2.2uH; Ind_H: 2.2E-6; Imax_A: 12.7; Irms: 12.7A @ 40C rise; Isat: 15.9A @ 30% inductance drop; DCR_ohm: 0.012; Value2: 12.7A; SizeAreaWB_mm2: 71.5616; SizeArea_mm2: 41.7216; SizeX_mm: 6.36; SizeY_mm: 6.56; SizeZ_mm: 3.1; AEC Category: Q200; Green_Lifecycle: Not Set; Green_REACh: Incomplete
Q5 = DXT2222A-13, Diodes Inc.: Transistor, NPN, 40 V, 0.6 A, SOT-89; SymbolCreator: a0412235; PNP: 0; NPN: 1; Vceo_V: 40; Value: 40 V; IcRated_A: 0.6; Value1: 0.6 A; HfeMax: 300; TaMin_C: -55; TaMax_C: 150; SizeAreaWB_mm2: 28.05; SizeArea_mm2: 18.45; SizeX_mm: 4.1; SizeY_mm: 4.5; SizeZ_mm: 1.5; CompType: BJT; U/M: EA; AEC Category: Q101; Green_Lifecycle: Active; Green_REACh: Passed
Q9 = CMP-0074796-1: Transistor, NPN, 1200 V, .1 A, TO-220AB; Manufacturer: STMicroelectronics; TaMin_C: -65°C; SizeAreaWB_mm2: 79.3; Value1: .1 A; Vceo_V: 1.2kV; U/M: EA; Value: 1200 V; TaMax_C: 150°C; IcRated_A: 1dA; SizeZ_mm: 19.4; SizeX_mm: 10.2; SizeY_mm: 4.5; SizeArea_mm2: 45.9; CompType: BJT; PNP: 0.0; AEC Qualified: N; NPN: 1.0; Vcesat1_V: 2V; AEC Category: Q101
Q10 = 2N7002-7-F: MOSFET, N-CH, 60 V, 0.17 A, SOT-23; Manufacturer: Diodes Inc.; Alternate Manufacturer: None; U/M: EA; ChType: N; Value: 60V; VdsMax_V: 60; Value1: 7.5 ohm; Rdson45_ohm: 7.5; Value2: 223 nC; QgTyp_nC: 223; Vgs_V: 20; IdsMax_A: 0.17; SizeAreaWB_mm2: 14; SizeX_mm: 2.5; SizeY_mm: 3; SizeZ_mm: 1.1; AEC Category: Q101; Green_Lifecycle: Active; Green_REACh: Passed
Q11 = PBSS4250X,115, Nexperia: Transistor, NPN, 50 V, 2 A, SOT-89; SymbolCreator: a0412235; PNP: 0; NPN: 1; Vceo_V: 50; Vcesat1_V: 0.25; Value: 50 V; IcRated_A: 2; Value1: 2 A; TaMin_C: -65; TaMax_C: 150; SizeAreaWB_mm2: 28.05; SizeArea_mm2: 18.45; SizeX_mm: 4.1; SizeY_mm: 4.5; SizeZ_mm: 1.5; CompType: BJT; U/M: EA; AEC Category: Q101; AEC Qualified: N
Q12 = MMBT2907ALT1G, ON Semiconductor: Transistor, PNP, 60 V, 0.6 A, SOT-23; CompType: BJT; PNP: 1; NPN: 0; Vceo_V: 60; Vcesat1_V: 1.6; Value: 60 V; IcRated_A: 0.6; Value1: 0.6 A; TaMin_C: -55; TaMax_C: 150; SizeAreaWB_mm2: 14; SizeArea_mm2: 7.5; SizeX_mm: 2.5; SizeY_mm: 3; SizeZ_mm: 1.1; U/M: EA; AEC Category: Q101; Green_Lifecycle: Active; Green_REACh: Passed
Q13 = BC817-16LT1G, ON Semiconductor: Transistor, NPN, 45 V, 0.5 A, SOT-23; CompType: BJT; PNP: 0; NPN: 1; Vceo_V: 45; Vcesat1_V: 0.7; Value: 45 V; IcRated_A: 0.5; Value1: 0.5 A; HfeMax: 250; TaMin_C: -65; TaMax_C: 150; SizeAreaWB_mm2: 14; SizeArea_mm2: 7.5; SizeX_mm: 2.5; SizeY_mm: 3; SizeZ_mm: 1.1; U/M: EA; AEC Category: Q101
Q14 = C2M1000170D: MOSFET, N-CH, 1700 V, 5 A, TO-247; Manufacturer: Cree; Alternate Manufacturer: None; U/M: EA; ChType: N; Value: 1700V; VdsMax_V: 1700; Value1: ? ohm; Value2: 13 nC; QgTyp_nC: 13; Vgs_V: 25; IdsMax_A: 5; SizeAreaWB_mm2: 123.2; SizeArea_mm2: 78; SizeX_mm: 15.6; AEC Category: Q101; Green_Lifecycle: Not Set; Green_REACh: Incomplete
Q15 = MMBT3904-7-F, Diodes Inc.: Transistor, NPN, 40 V, 0.2 A, SOT-23; CompType: BJT; PNP: 0; NPN: 1; Vceo_V: 40; Vcesat1_V: 0.2; Value: 40 V; Value1: 0.2 A; HfeMax: 400; TaMin_C: -55; TaMax_C: 150; SizeAreaWB_mm2: 14; SizeArea_mm2: 7.5; SizeX_mm: 2.5; SizeY_mm: 3; SizeZ_mm: 1.1; U/M: EA; AEC Category: Q101; Green_Lifecycle: Active; Green_REACh: Passed
Q16 = BC807-40LT1G, ON Semiconductor: Transistor, PNP, 45 V, 0.5 A, AEC-Q101, SOT-23; CompType: BJT; PNP: 1; NPN: 0; Vceo_V: 45; Vcesat1_V: 0.7; Value: 45 V; IcRated_A: 0.5; Value1: 0.5 A; HfeMax: 600; TaMin_C: -55; TaMax_C: 150; SizeAreaWB_mm2: 14; SizeArea_mm2: 7.5; SizeX_mm: 2.5; SizeY_mm: 3; SizeZ_mm: 1.1; U/M: EA; AEC Category: Q101; AEC Qualified: Y
Q19 = BSS84-7-F: MOSFET, P-CH, -50 V, -0.13 A, SOT-23; Manufacturer: Diodes Inc.; Alternate Manufacturer: None; U/M: EA; ChType: P; Value: -50V; Value1: ? ohm; Value2: ? nC; Vgs_V: -20; SizeAreaWB_mm2: 14; SizeArea_mm2: 7.5; SizeX_mm: 2.5; SizeY_mm: 3; SizeZ_mm: 1.1; AEC Category: Q101; AEC Qualified: N; Green_Lifecycle: Active; Green_REACh: Passed
Q20 = 2N7002K-T1-E3: MOSFET, N-CH, 60 V, 0.3 A, SOT-23; Manufacturer: Vishay-Siliconix; Alternate Manufacturer: None; SymbolCreator: a0411947; U/M: EA; ChType: N; Value: 60V; VdsMax_V: 60; Value1: 4 ohm; Rdson45_ohm: 4; Value2: 0.4 nC; QgTyp_nC: 0.4; Vgs_V: 20; IdsMax_A: 0.3; SizeAreaWB_mm2: 14; SizeArea_mm2: 7.5; SizeX_mm: 2.5; SizeY_mm: 3; SizeZ_mm: 1.1; AEC Category: Q101; Green_Lifecycle: Active; Green_REACh: Passed
R36 = CMP-0016044-2: RES, 0, 5%, 0.75 W, AEC-Q200 Grade 0, 2010; Manufacturer: Vishay-Dale; Power_W: 750mW; TempCo: ppm/C; Value_Code: 0000; U/M: EA; Value: 0; EIA_Code: E24; SizeX_mm: 5; SizeY_mm: 2.5; SizeZ_mm: 1.66; Value2: 0.75W; SizeArea_mm2: 12.5; AEC Qualified: Y; AEC Category: Q200
R37 R39 R41 R44 R48 R49 = CMP-0077778-1: RES, 1.5 M, 5%, 0.75 W, AEC-Q200 Grade 0, 2010; Manufacturer: Panasonic; Power_W: 750mW; Value_Code: 1M50; U/M: EA; Value: 1.5Meg; EIA_Code: E24; SizeX_mm: 5.0; SizeY_mm: 2.5; SizeZ_mm: 1.66; Value2: 0.75W; SizeArea_mm2: 12.5; CompType: Resistor; AEC Qualified: Y; VDC_V: 200V; AEC Grade: 0; AEC Category: Q200
R38 R40 R42 R43 R45 R46 = CRCW201049K9FKEF: RES, 49.9 k, 1%, 0.75 W, AEC-Q200 Grade 0, 2010; Manufacturer: Vishay-Dale; CompType: Resistor; Value: 49.9k; Res_ohm: 49900; Value_Code: 49k9; Tolerance_%: 1; Power_W: 0.75; Value2: 0.75W; VDC_V: 400; TempCo: 100 ppm/C; SizeArea_mm2: 12.5; SizeX_mm: 5; SizeY_mm: 2.5; SizeZ_mm: 1.66; EIA_Code: E96; U/M: EA; AEC Category: Q200; AEC Qualified: Y; AEC Grade: 0
R47 = CRCW201033R0JNEF: RES, 33, 5%, 0.75 W, AEC-Q200 Grade 0, 2010; Manufacturer: Vishay-Dale; CompType: Resistor; Value: 33; Value_Code: 33R0; Tolerance_%: 5; Power_W: 0.75; Value2: 0.75W; VDC_V: 400; TempCo: 200 ppm/C; SizeArea_mm2: 12.5; SizeY_mm: 2.5; SizeZ_mm: 1.66; EIA_Code: E24; U/M: EA; AEC Category: Q200; AEC Qualified: Y; AEC Grade: 0
R50 R51 = CRCW20101M00FKEF: RES, 1.00 M, 1%, 0.75 W, AEC-Q200 Grade 0, 2010; Manufacturer: Vishay-Dale; CompType: Resistor; Value: 1.00Meg; Res_ohm: 1000000; Value_Code: 1M00; Tolerance_%: 1; Power_W: 0.75; Value2: 0.75W; VDC_V: 400; TempCo: 100 ppm/C; SizeArea_mm2: 12.5; SizeX_mm: 5; SizeY_mm: 2.5; SizeZ_mm: 1.66; EIA_Code: E96; U/M: EA; AEC Category: Q200; AEC Qualified: Y; AEC Grade: 0
R52 R61 = CRCW08052K00FKEA: RES, 2.00 k, 1%, 0.125 W, 0805; Manufacturer: Vishay-Dale; CompType: Resistor; Value: 2.00k; Res_ohm: 2000; Value_Code: 2k00; Tolerance_%: 1; Power_W: 0.125; Value2: 0.125W; VDC_V: 150; TempCo: 100 ppm/C; SizeArea_mm2: 2.5; SizeX_mm: 2; SizeY_mm: 1.25; SizeZ_mm: 1.45; EIA_Code: E96; U/M: EA; AEC Category: Q200; Green_Lifecycle: Active; Green_REACh: Passed
R54 = CRCW0603499KFKEA: RES, 499 k, 1%, 0.1 W, 0603; Manufacturer: Vishay-Dale; CompType: Resistor; Value: 499k; Res_ohm: 499000; Tolerance_%: 1; Power_W: 0.1; Value2: 0.1W; VDC_V: 75; TempCo: 100 ppm/C; SizeArea_mm2: 1.28; SizeX_mm: 1.6; SizeY_mm: 0.8; EIA_Code: E96; U/M: EA; AEC Category: Q200; Green_Lifecycle: Active; Green_REACh: Passed
R55 = CRCW06034K70JNEA: RES, 4.7 k, 5%, 0.1 W, 0603; Manufacturer: Vishay-Dale; CompType: Resistor; Value: 4.7k; Res_ohm: 4700; Value_Code: 4k70; Tolerance_%: 5; Power_W: 0.1; Value2: 0.1W; VDC_V: 75; TempCo: 200 ppm/C; SizeArea_mm2: 1.28; SizeX_mm: 1.6; SizeY_mm: 0.8; SizeZ_mm: 1; EIA_Code: E24; U/M: EA; AEC Category: Q200; Green_Lifecycle: Active; Green_REACh: Passed
R56 = CMP-0021998-2: RES, 10.0 k, 1%, 0.1 W, 0603; Manufacturer: Vishay-Dale; Power_W: 100mW; TempCo: 100 ppm/C; Value_Code: 10k0; U/M: EA; Value: 10.0k; EIA_Code: E96; Res_ohm: 10k; SizeX_mm: 1.6; SizeY_mm: 0.8; SizeZ_mm: 1; Value2: 0.1W; SizeArea_mm2: 1.28; VDC_V: 75V; AEC Category: Q200
R57 = CRCW080520K0FKEA: RES, 20.0 k, 1%, 0.125 W, 0805; Manufacturer: Vishay-Dale; CompType: Resistor; Value: 20.0k; Res_ohm: 20000; Value_Code: 20k0; Tolerance_%: 1; Power_W: 0.125; Value2: 0.125W; VDC_V: 150; TempCo: 100 ppm/C; SizeArea_mm2: 2.5; SizeX_mm: 2; SizeY_mm: 1.25; SizeZ_mm: 1.45; EIA_Code: E96; U/M: EA; AEC Category: Q200; Green_Lifecycle: Active; Green_REACh: Passed
R58 R59 R81 = CRCW08050000Z0EA: RES, 0, 5%, 0.125 W, 0805; Manufacturer: Vishay-Dale; CompType: Resistor; Value: 0; Value_Code: 0000; Tolerance_%: 5; Power_W: 0.125; Value2: 0.125W; VDC_V: 150; TempCo: 200 ppm/C; SizeArea_mm2: 2.5; SizeX_mm: 2; SizeY_mm: 1.25; SizeZ_mm: 1.45; EIA_Code: E24; U/M: EA; AEC Category: Q200; Green_Lifecycle: Active; Green_REACh: Passed
R60 = CRCW080513K0FKEA: RES, 13.0 k, 1%, 0.125 W, 0805; Manufacturer: Vishay-Dale; CompType: Resistor; Value: 13.0k; Res_ohm: 13000; Value_Code: 13k0; Tolerance_%: 1; Power_W: 0.125; Value2: 0.125W; VDC_V: 150; TempCo: 100 ppm/C; SizeArea_mm2: 2.5; SizeX_mm: 2; SizeY_mm: 1.25; SizeZ_mm: 1.45; EIA_Code: E96; U/M: EA; AEC Category: Q200
R62 = CRCW08051K24FKEA: RES, 1.24 k, 1%, 0.125 W, 0805; Manufacturer: Vishay-Dale; CompType: Resistor; Value: 1.24k; Res_ohm: 1240; Value_Code: 1k24; Tolerance_%: 1; Power_W: 0.125; Value2: 0.125W; VDC_V: 150; TempCo: 100 ppm/C; SizeArea_mm2: 2.5; SizeX_mm: 2; SizeY_mm: 1.25; SizeZ_mm: 1.45; EIA_Code: E96; U/M: EA; AEC Category: Q200
R63 R75 = CRCW08051K00FKEA: RES, 1.00 k, 1%, 0.125 W, 0805; Manufacturer: Vishay-Dale; CompType: Resistor; Value: 1.00k; Res_ohm: 1000; Value_Code: 1k00; Tolerance_%: 1; Power_W: 0.125; Value2: 0.125W; VDC_V: 150; TempCo: 100 ppm/C; SizeArea_mm2: 2.5; SizeX_mm: 2; SizeY_mm: 1.25; SizeZ_mm: 1.45; EIA_Code: E96; U/M: EA; AEC Category: Q200; Green_Lifecycle: Active; Green_REACh: Passed
R64 = CRCW080549R9FKEA: RES, 49.9, 1%, 0.125 W, 0805; Manufacturer: Vishay-Dale; CompType: Resistor; Value: 49.9; Value_Code: 49R9; Tolerance_%: 1; Power_W: 0.125; Value2: 0.125W; VDC_V: 150; TempCo: 100 ppm/C; SizeArea_mm2: 2.5; SizeX_mm: 2; SizeY_mm: 1.25; SizeZ_mm: 1.45; EIA_Code: E96; U/M: EA; AEC Category: Q200; Green_Lifecycle: Active; Green_REACh: Passed
R65 = CRCW080510K2FKEA: RES, 10.2 k, 1%, 0.125 W, 0805; Manufacturer: Vishay-Dale; CompType: Resistor; Value: 10.2k; Res_ohm: 10200; Value_Code: 10k2; Tolerance_%: 1; Power_W: 0.125; Value2: 0.125W; VDC_V: 150; TempCo: 100 ppm/C; SizeArea_mm2: 2.5; SizeX_mm: 2; SizeY_mm: 1.25; SizeZ_mm: 1.45; EIA_Code: E96; U/M: EA; AEC Category: Q200; Green_Lifecycle: Active; Green_REACh: Passed
R66 = CRCW120610K0FKEA: RES, 10.0 k, 1%, 0.25 W, 1206; Manufacturer: Vishay-Dale; CompType: Resistor; Value: 10.0k; Res_ohm: 10000; Value_Code: 10k0; Tolerance_%: 1; Power_W: 0.25; Value2: 0.25W; VDC_V: 200; TempCo: 100 ppm/C; SizeArea_mm2: 5.12; SizeX_mm: 3.2; SizeY_mm: 1.6; SizeZ_mm: 1.35; EIA_Code: E96; U/M: EA; AEC Category: Q200; Green_Lifecycle: Active; Green_REACh: Passed
R67 R68 = CRM2010-FX-R910ELF: RES, 0.91, 1%, 1 W, 2010; Manufacturer: Bourns; CompType: Resistor; Value: 0.91; Value_Code: R910; Tolerance_%: 1; Value2: 1W; TempCo: 100 ppm/C; SizeArea_mm2: 12.5; SizeX_mm: 5; SizeY_mm: 2.5; SizeZ_mm: 1.66; EIA_Code: E96; U/M: EA; AEC Category: Q200
R69 = CRCW080512K4FKEA: RES, 12.4 k, 1%, 0.125 W, 0805; Manufacturer: Vishay-Dale; CompType: Resistor; Value: 12.4k; Res_ohm: 12400; Value_Code: 12k4; Tolerance_%: 1; Power_W: 0.125; Value2: 0.125W; VDC_V: 150; TempCo: 100 ppm/C; SizeArea_mm2: 2.5; SizeX_mm: 2; SizeY_mm: 1.25; SizeZ_mm: 1.45; EIA_Code: E96; U/M: EA; AEC Category: Q200; Green_Lifecycle: Active; Green_REACh: Passed
R70 = CRCW08056K80JNEA: RES, 6.8 k, 5%, 0.125 W, 0805; Manufacturer: Vishay-Dale; CompType: Resistor; Value: 6.8k; Res_ohm: 6800; Value_Code: 6k80; Tolerance_%: 5; Power_W: 0.125; Value2: 0.125W; VDC_V: 150; TempCo: 200 ppm/C; SizeArea_mm2: 2.5; SizeX_mm: 2; SizeY_mm: 1.25; SizeZ_mm: 1.45; EIA_Code: E24; U/M: EA; AEC Category: Q200
R71 = CRCW08059K09FKEA: RES, 9.09 k, 1%, 0.125 W, 0805; Manufacturer: Vishay-Dale; CompType: Resistor; Value: 9.09k; Res_ohm: 9090; Value_Code: 9k09; Tolerance_%: 1; Power_W: 0.125; Value2: 0.125W; VDC_V: 150; TempCo: 100 ppm/C; SizeArea_mm2: 2.5; SizeX_mm: 2; SizeY_mm: 1.25; SizeZ_mm: 1.45; EIA_Code: E96; U/M: EA; AEC Category: Q200
R72 = CRCW08052K20JNEA: RES, 2.2 k, 5%, 0.125 W, 0805; Manufacturer: Vishay-Dale; CompType: Resistor; Value: 2.2k; Res_ohm: 2200; Value_Code: 2k20; Tolerance_%: 5; Power_W: 0.125; Value2: 0.125W; VDC_V: 150; TempCo: 200 ppm/C; SizeArea_mm2: 2.5; SizeX_mm: 2; SizeY_mm: 1.25; SizeZ_mm: 1.45; EIA_Code: E24; U/M: EA; AEC Category: Q200
R73 = CRCW08052K43FKEA: RES, 2.43 k, 1%, 0.125 W, 0805; Manufacturer: Vishay-Dale; CompType: Resistor; Value: 2.43k; Res_ohm: 2430; Value_Code: 2k43; Tolerance_%: 1; Power_W: 0.125; Value2: 0.125W; VDC_V: 150; TempCo: 100 ppm/C; SizeArea_mm2: 2.5; SizeX_mm: 2; SizeY_mm: 1.25; SizeZ_mm: 1.45; EIA_Code: E96; U/M: EA; AEC Category: Q200
R74 = CRCW08054K99FKEA: RES, 4.99 k, 1%, 0.125 W, 0805; Manufacturer: Vishay-Dale; CompType: Resistor; Value: 4.99k; Res_ohm: 4990; Value_Code: 4k99; Tolerance_%: 1; Power_W: 0.125; Value2: 0.125W; VDC_V: 150; TempCo: 100 ppm/C; SizeArea_mm2: 2.5; SizeX_mm: 2; SizeY_mm: 1.25; SizeZ_mm: 1.45; EIA_Code: E96; U/M: EA; AEC Category: Q200; Green_Lifecycle: Active; Green_REACh: Passed
R79 R91 = CRCW1206100RFKEA: RES, 100, 1%, 0.25 W, 1206; Manufacturer: Vishay-Dale; CompType: Resistor; Value: 100; Value_Code: 100R; Tolerance_%: 1; Power_W: 0.25; Value2: 0.25W; VDC_V: 200; TempCo: 100 ppm/C; SizeArea_mm2: 5.12; SizeX_mm: 3.2; SizeY_mm: 1.6; SizeZ_mm: 1.35; EIA_Code: E96; U/M: EA; AEC Category: Q200; Green_Lifecycle: Active; Green_REACh: Passed
R80 R95 = CRCW120610R0FKEA: RES, 10.0, 1%, 0.25 W, 1206; Manufacturer: Vishay-Dale; CompType: Resistor; Value: 10.0; Res_ohm: 10; Value_Code: 10R0; Tolerance_%: 1; Power_W: 0.25; Value2: 0.25W; VDC_V: 200; TempCo: 100 ppm/C; SizeArea_mm2: 5.12; SizeX_mm: 3.2; SizeY_mm: 1.6; SizeZ_mm: 1.35; EIA_Code: E96; U/M: EA; AEC Category: Q200; Green_Lifecycle: Active; Green_REACh: Passed
R82 = CRCW080540K2FKEA: RES, 40.2 k, 1%, 0.125 W, 0805; Manufacturer: Vishay-Dale; CompType: Resistor; Value: 40.2k; Res_ohm: 40200; Value_Code: 40k2; Tolerance_%: 1; Power_W: 0.125; Value2: 0.125W; VDC_V: 150; TempCo: 100 ppm/C; SizeArea_mm2: 2.5; SizeX_mm: 2; SizeY_mm: 1.25; SizeZ_mm: 1.45; EIA_Code: E96; U/M: EA; AEC Category: Q200; Green_Lifecycle: Active; Green_REACh: Passed
R83 = CRCW08052K05FKEA: RES, 2.05 k, 1%, 0.125 W, 0805; Manufacturer: Vishay-Dale; CompType: Resistor; Value: 2.05k; Res_ohm: 2050; Value_Code: 2k05; Tolerance_%: 1; Power_W: 0.125; Value2: 0.125W; VDC_V: 150; TempCo: 100 ppm/C; SizeArea_mm2: 2.5; SizeX_mm: 2; SizeY_mm: 1.25; SizeZ_mm: 1.45; EIA_Code: E96; U/M: EA; AEC Category: Q200
R85 = CRCW0805374RFKEA: RES, 374, 1%, 0.125 W, 0805; Manufacturer: Vishay-Dale; CompType: Resistor; Value: 374; Value_Code: 374R; Tolerance_%: 1; Power_W: 0.125; Value2: 0.125W; VDC_V: 150; TempCo: 100 ppm/C; SizeArea_mm2: 2.5; SizeX_mm: 2; SizeY_mm: 1.25; SizeZ_mm: 1.45; EIA_Code: E96; U/M: EA; AEC Category: Q200; Green_Lifecycle: Active; Green_REACh: Passed
R86 R92 = CRCW20101K50FKEF: RES, 1.50 k, 1%, 0.75 W, AEC-Q200 Grade 0, 2010; Manufacturer: Vishay-Dale; CompType: Resistor; Value: 1.50k; Res_ohm: 1500; Value_Code: 1k50; Tolerance_%: 1; Power_W: 0.75; Value2: 0.75W; VDC_V: 400; TempCo: 100 ppm/C; SizeArea_mm2: 12.5; SizeX_mm: 5; SizeY_mm: 2.5; SizeZ_mm: 1.66; EIA_Code: E96; U/M: EA; AEC Category: Q200; AEC Qualified: Y; AEC Grade: 0
R87 = CRCW08053K01FKEA: RES, 3.01 k, 1%, 0.125 W, 0805; Manufacturer: Vishay-Dale; CompType: Resistor; Value: 3.01k; Res_ohm: 3010; Value_Code: 3k01; Tolerance_%: 1; Power_W: 0.125; Value2: 0.125W; VDC_V: 150; TempCo: 100 ppm/C; SizeArea_mm2: 2.5; SizeX_mm: 2; SizeY_mm: 1.25; SizeZ_mm: 1.45; EIA_Code: E96; U/M: EA; AEC Category: Q200; Green_Lifecycle: Active; Green_REACh: Passed
R88 = CRCW0805100RFKEA: RES, 100, 1%, 0.125 W, 0805; Manufacturer: Vishay-Dale; CompType: Resistor; Value: 100; Value_Code: 100R; Tolerance_%: 1; Power_W: 0.125; Value2: 0.125W; VDC_V: 150; TempCo: 100 ppm/C; SizeArea_mm2: 2.5; SizeX_mm: 2; SizeY_mm: 1.25; SizeZ_mm: 1.45; EIA_Code: E96; U/M: EA; AEC Category: Q200; Green_Lifecycle: Active; Green_REACh: Passed
R89 = CRCW20102R00FKEF: RES, 2.00, 1%, 0.75 W, AEC-Q200 Grade 0, 2010; Manufacturer: Vishay-Dale; CompType: Resistor; Value: 2.00; Res_ohm: 2; Value_Code: 2R00; Tolerance_%: 1; Power_W: 0.75; Value2: 0.75W; VDC_V: 400; TempCo: 100 ppm/C; SizeArea_mm2: 12.5; SizeX_mm: 5; SizeY_mm: 2.5; SizeZ_mm: 1.66; EIA_Code: E96; U/M: EA; AEC Category: Q200; AEC Qualified: Y; AEC Grade: 0
R93 = CRCW080537R4FKEA: RES, 37.4, 1%, 0.125 W, 0805; Manufacturer: Vishay-Dale; CompType: Resistor; Value: 37.4; Value_Code: 37R4; Tolerance_%: 1; Power_W: 0.125; Value2: 0.125W; VDC_V: 150; TempCo: 100 ppm/C; SizeArea_mm2: 2.5; SizeX_mm: 2; SizeY_mm: 1.25; SizeZ_mm: 1.45; EIA_Code: E96; U/M: EA; AEC Category: Q200
R94 = CRCW0805499RFKEA: RES, 499, 1%, 0.125 W, 0805; Manufacturer: Vishay-Dale; CompType: Resistor; Value: 499; Value_Code: 499R; Tolerance_%: 1; Power_W: 0.125; Value2: 0.125W; VDC_V: 150; TempCo: 100 ppm/C; SizeArea_mm2: 2.5; SizeX_mm: 2; SizeY_mm: 1.25; SizeZ_mm: 1.45; EIA_Code: E96; U/M: EA; AEC Category: Q200; Green_Lifecycle: Active; Green_REACh: Passed
R96 = CRCW0805237RFKEA: RES, 237, 1%, 0.125 W, 0805; Manufacturer: Vishay-Dale; CompType: Resistor; Value: 237; Value_Code: 237R; Tolerance_%: 1; Power_W: 0.125; Value2: 0.125W; VDC_V: 150; TempCo: 100 ppm/C; SizeArea_mm2: 2.5; SizeX_mm: 2; SizeY_mm: 1.25; SizeZ_mm: 1.45; EIA_Code: E96; U/M: EA; AEC Category: Q200
R97 = CRCW0805470RFKEA: RES, 470, 1%, 0.125 W, 0805; Manufacturer: Vishay-Dale; CompType: Resistor; Value: 470; Value_Code: 470R; Tolerance_%: 1; Power_W: 0.125; Value2: 0.125W; VDC_V: 150; TempCo: 100 ppm/C; SizeArea_mm2: 2.5; SizeX_mm: 2; SizeY_mm: 1.25; SizeZ_mm: 1.45; U/M: EA; AEC Category: Q200
R98 = CRCW12064R70JNEA: RES, 4.7, 5%, 0.25 W, 1206; Manufacturer: Vishay-Dale; CompType: Resistor; Value: 4.7; Value_Code: 4R70; Tolerance_%: 5; Power_W: 0.25; Value2: 0.25W; VDC_V: 200; TempCo: 200 ppm/C; SizeArea_mm2: 5.12; SizeX_mm: 3.2; SizeY_mm: 1.6; SizeZ_mm: 1.35; EIA_Code: E24; U/M: EA; AEC Category: Q200; Green_Lifecycle: Active; Green_REACh: Passed
T2 = CMP-0077115-3: Transformer, 1500 uH, SMT; Manufacturer: Coilcraft; SizeX_mm: 40; SizeZ_mm: 13.9; AEC Qualified: N; Value: 1.5mH; SizeArea_mm2: 1600; AEC Category: Q200; SizeAreaWB_mm2: 1764; Lp: 1500.0; Ns1toNp: 0.083
TP9 TP11 TP14 = 5005: Test Point, Compact, Red, TH; Manufacturer: Keystone; CompType: Test Point Loop; ContactFinish: Silver; Green_Lifecycle: Active; Green_REACh: Passed
TP10 TP15 = 5122: Test Point, Compact, Blue, TH; Manufacturer: Keystone; CompType: Test Point Loop; U/M: EA; ContactFinish: Silver; Green_Lifecycle: Active; Green_REACh: Passed
TP16 = 5006: Test Point, Compact, Black, TH; Manufacturer: Keystone; CompType: Test Point Loop; ContactFinish: Silver; Green_Lifecycle: Active; Green_REACh: Passed
U2 = CMP-0074855-1: Automotive Catalog BiCMOS Low-Power Current Mode PWM Controller, D0008A (SOIC-8); Alternate Manufacturer: Texas Instruments; SizeAreaWB_mm2: 56.58; U/M: EA; SizeZ_mm: 1.75; SizeX_mm: 4.9; SizeY_mm: 6.2; SizeArea_mm2: 30.38; CompType: IC
U3 = CMP-0006181-2: Optocoupler, 5 kV, 80-160% CTR, SMT; Manufacturer: Fairchild Semiconductor; CTR (Max): 160%; CTR (Min): 80%; Voltage_Isolation_Vrms: 5kV
U4 = CMP-0033164-1: Automotive Catalog Adjustable Precision Shunt Regulator, 34 ppm / degC, 100 mA, -40 to 125 degC, 3-pin SOT-23 (DBZ), Green (RoHS & no Sb/Br); Manufacturer: Texas Instruments; SubFamily: Shunt Voltage Reference; Initial Accuracy @ 25/deg C(%): 1; Min Iz for Regulation(uA): 600; Iout/Iz(Max)(mA): 100; Temp Coeff(Typ)(ppm/ degree C): 34; VO Adj(Max)(V): 36; VO Adj(Min)(V): 2.495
